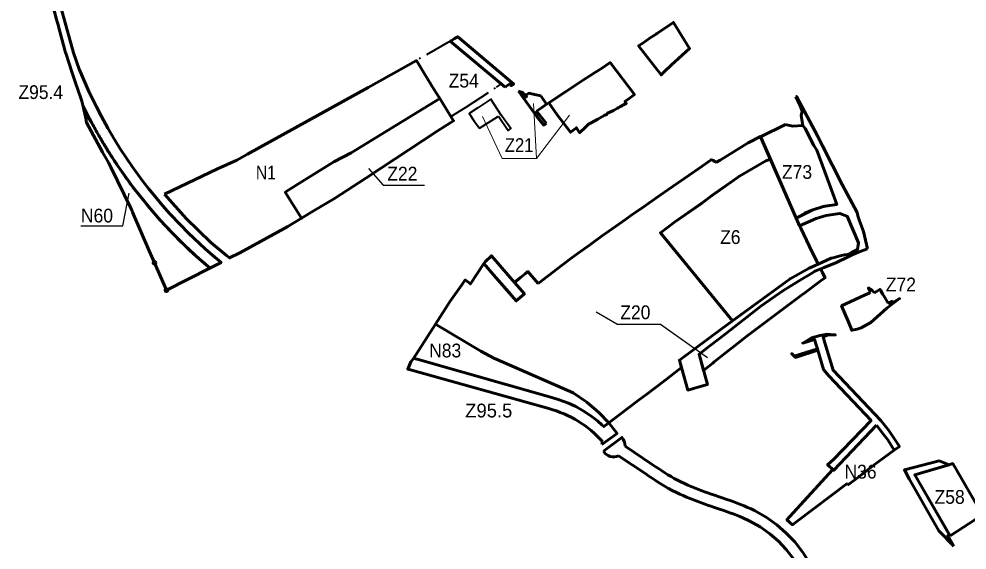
# Model space of a CAD drawing. Extents: x -650277 to -643422, y -1073980 to -1066720.
# Drawn here: x -649120 to -647467, y -1071620 to -1070696 of the extents above; entities that cross this region are included whole.
import ezdxf

# ---------------------------------------------------------------- set-up
doc = ezdxf.new("R2010")
doc.units = 0
doc.header["$LTSCALE"] = 9.6
doc.header["$PDMODE"] = 32
doc.header["$PDSIZE"] = 4.8
doc.linetypes.add('DOT_DASHED', pattern=[7.7, 5, -1.2, 0.3, -1.2])
for name, color, linetype, lineweight in [('1', 7, 'Continuous', 60), ('15', 7, 'Continuous', 60), ('18', 7, 'Continuous', 60), ('42', 7, 'Continuous', 60), ('60', 7, 'Continuous', 60), ('63', 7, 'Continuous', 25), ('7', 7, 'Continuous', 60), ('9', 7, 'Continuous', 60)]:
    doc.layers.add(name, color=color, linetype=linetype, lineweight=lineweight)

msp = doc.modelspace()

# ---------------------------------------------------------------- linework, layer by layer
at = {"layer": '1'}
for points in [[(-648032.601, -1070737.472), (-648039.82, -1070742.33), (-648000.85, -1070792.88), (-647994.63, -1070787.05), (-647982.89, -1070776.05), (-647976.97, -1070770.51), (-647964.21, -1070758.77), (-647951.11, -1070746.78), (-647979.17, -1070701.65), (-648008.28, -1070720.96), (-648009.29, -1070721.79), (-648019.49, -1070728.65)], [(-648540.7, -1070928.6), (-648571.14, -1070944.67), (-648634.07, -1070983.17), (-648655.76, -1070997.5), (-648627.39, -1071042.65), (-648605.3, -1071029.34), (-648570.23, -1071008.2), (-648515.46, -1070972.94), (-648389.33, -1070889.79), (-648362.519, -1070872.788), (-648386.587, -1070833.807), (-648479.18, -1070891.26)], [(-648215.08, -1071156.35), (-648232.8, -1071135.6), (-648237.46, -1071139.38), (-648245.49, -1071145.91), (-648256.04, -1071154.5), (-648238.84, -1071174.33), (-648253.126, -1071186.542), (-648292.587, -1071141.054), (-648309.41, -1071121.655), (-648333.002, -1071157.07), (-648341.943, -1071150.071), (-648347.949, -1071158.385), (-648368.48, -1071186.81), (-648394.104, -1071227.17), (-648315.127, -1071274.052), (-648292.406, -1071286.112), (-648274.918, -1071293.751), (-648154.21, -1071346.477), (-648130, -1071363), (-648109, -1071381), (-648091.92, -1071399.07), (-648060.01, -1071374.69), (-648038.18, -1071358.51), (-648025.39, -1071348.76), (-647994.31, -1071325.03), (-647965.26, -1071302.86), (-647966.226, -1071299.385), (-647968.896, -1071289.779), (-647916.208, -1071250.662), (-647895.959, -1071235.746), (-647875.939, -1071221.104), (-648001.922, -1071067.83), (-647977.41, -1071049.74), (-647930.96, -1071017.383), (-647912.11, -1071003.11), (-647864.29, -1070969.503), (-647818.33, -1070942.91), (-647810.243, -1070939.825), (-647827.527, -1070900.351), (-647848.89, -1070911.21), (-647897.76, -1070941.62), (-647904.13, -1070944.78), (-647909.42, -1070942.63), (-647908.63, -1070942.1), (-647913.45, -1070940.79), (-647934.9, -1070955.87), (-647952.01, -1070967.82), (-647970.19, -1070980.45), (-647988.81, -1070993.27), (-648008.34, -1071006.32), (-648030.24, -1071021.91), (-648044.82, -1071032.25), (-648051.48, -1071036.97), (-648062.53, -1071044.59), (-648085.73, -1071060.92), (-648097.61, -1071069.37), (-648102.55, -1071072.86), (-648125.53, -1071089.51), (-648141.12, -1071100.71), (-648155.77, -1071111.23), (-648172.48, -1071123.95), (-648197.57, -1071143.03)], [(-648001.922, -1071067.83), (-647977.41, -1071049.74), (-647930.7, -1071017.18), (-647911.838, -1071002.919), (-647864.03, -1070969.3), (-647864.03, -1070969.3), (-647818.33, -1070942.91), (-647810.243, -1070939.825), (-647759.52, -1071055.67), (-647757.19, -1071059.66), (-647742.64, -1071090.72), (-647726.74, -1071122.48), (-647742.35, -1071129.43), (-647775.982, -1071148.001), (-647775.982, -1071148.001), (-647875.939, -1071221.104)], [(-647756.03, -1071176.76), (-647750.34, -1071172.5), (-647726.56, -1071154.68), (-647723.79, -1071152.61), (-647720.85, -1071150.41), (-647714.71, -1071146.51), (-647719.73, -1071136.48), (-647722.51, -1071130.93), (-647732.58, -1071135.04), (-647733.38, -1071135.37), (-647737.027, -1071137.593), (-647761.366, -1071152.304), (-647788.66, -1071168.8), (-647826.56, -1071195.86), (-647889.22, -1071244.48), (-647915.6, -1071264.95), (-647934.6, -1071279.45), (-647926.69, -1071307.81), (-647910.73, -1071295.08), (-647907.92, -1071292.84), (-647888.77, -1071277.56), (-647873.25, -1071265.17), (-647850.956, -1071248.208)]]:
    msp.add_lwpolyline(points, close=True, dxfattribs=at)
at = {"layer": '1', "linetype": 'DOT_DASHED', "lineweight": 40}
msp.add_lwpolyline([(-648368.163, -1070734.376), (-648427.25, -1070767.95), (-648366.98, -1070865.44), (-648341.58, -1070849.98), (-648287.74, -1070814.32), (-648282.44, -1070810.84), (-648278.832, -1070808.761)], close=True, dxfattribs=at)
at = {"layer": '1'}
for points in [[(-648095.42, -1070860.3), (-648083.65, -1070854.89), (-648076.73, -1070851.07), (-648074.41, -1070849.79), (-648072.59, -1070848.79), (-648065.35, -1070844.8), (-648061.52, -1070842.68), (-648063.76, -1070839.49), (-648056.61, -1070834.26), (-648047.17, -1070827.35), (-648089.27, -1070771.57), (-648104.78, -1070781.65), (-648114.77, -1070788.08), (-648125.2, -1070794.79), (-648136.08, -1070801.79)], [(-648136.08, -1070801.79), (-648151.77, -1070812.11), (-648167.6, -1070822.53), (-648196.65, -1070841.7), (-648181.75, -1070862.74), (-648158.58, -1070892.98), (-648148.34, -1070884.92), (-648142.79, -1070893.78), (-648133.14, -1070884.6), (-648127, -1070878.75), (-648122.72, -1070876.44), (-648111.24, -1070870.11), (-648099.85, -1070863.82), (-648094.9, -1070861.09), (-648095.42, -1070860.3)], [(-648237.46, -1070829.68), (-648241.96, -1070823.46), (-648249.5, -1070821.08)], [(-648249.5, -1070821.08), (-648222.158, -1070859.221), (-648217.1, -1070865.56), (-648205.18, -1070880.5), (-648200.86, -1070877.05)], [(-648210.517, -1070829.445), (-648221.58, -1070827.03), (-648231.22, -1070824.92), (-648237.46, -1070829.68)], [(-648218.11, -1070856.44), (-648209.37, -1070850.44), (-648200.17, -1070844.094), (-648210.517, -1070829.445)], [(-648200.86, -1070877.05), (-648212.94, -1070862.74), (-648217.85, -1070856.93), (-648218.11, -1070856.44)]]:
    msp.add_lwpolyline(points, dxfattribs=at)
at = {"layer": '1', "lineweight": 40}
for points in [[(-648284.02, -1070864.91), (-648267.24, -1070889.9), (-648262.4, -1070886.58), (-648279.39, -1070862.98), (-648297.39, -1070835.36), (-648320.02, -1070850.16), (-648335.19, -1070860.49), (-648326.41, -1070873.55), (-648317.14, -1070885.48)], [(-648317.14, -1070885.48), (-648285.72, -1070865.96), (-648284.02, -1070864.91)]]:
    msp.add_lwpolyline(points, dxfattribs=at)
at = {"layer": '1'}
msp.add_point((-648237.46, -1070829.68), dxfattribs=at)
at = {"layer": '15'}
msp.add_line((-648272.453, -1070814.072), (-648271.1, -1070813.17), dxfattribs=at)
for points in [[(-648271.1, -1070813.17), (-648267.8, -1070810.96), (-648264.38, -1070808.66), (-648262.15, -1070811.96), (-648257.61, -1070808.91), (-648355.275, -1070726.455), (-648360.83, -1070729.87), (-648366.739, -1070733.501), (-648368.163, -1070734.376), (-648272.453, -1070814.072)], [(-647659.01, -1071032.66), (-647685.1, -1070983.93), (-647719.06, -1070916.45), (-647728.35, -1070899.11), (-647764.84, -1070830.47), (-647765.72, -1070830.64)], [(-647765.72, -1070830.64), (-647759.08, -1070845.74), (-647755.87, -1070853.02), (-647754.6, -1070856.11), (-647756.45, -1070863.95), (-647753.81, -1070881.3)], [(-647753.81, -1070881.3), (-647749.75, -1070886.1), (-647734.48, -1070915.94), (-647729.27, -1070924.35), (-647701.45, -1070999.4)], [(-647701.45, -1070999.4), (-647694.54, -1071018.549), (-647718, -1071022), (-647736, -1071028), (-647750, -1071034), (-647765.408, -1071042.223), (-647759.52, -1071055.67), (-647730.17, -1071043.21), (-647712.74, -1071037.99), (-647688.9, -1071034.18), (-647676.96, -1071039.014)], [(-647676.96, -1071039.014), (-647676.9, -1071039.03), (-647676.45, -1071039.22), (-647656.443, -1071085.369), (-647658.55, -1071097.02), (-647669.02, -1071102.33), (-647667.35, -1071106.38), (-647655.47, -1071100.98), (-647640.727, -1071095.819)], [(-647640.727, -1071095.819), (-647648.106, -1071065.551), (-647654.747, -1071047.095), (-647657.699, -1071038.232), (-647659.01, -1071032.66)], [(-647498.271, -1071593.544), (-647558.654, -1071489.738), (-647498.8, -1071471.94), (-647515.87, -1071465.25), (-647576.471, -1071481.091), (-647568.35, -1071496.656), (-647516.376, -1071586.89), (-647490.561, -1071613.609)], [(-647490.561, -1071613.609), (-647493.6, -1071608.5), (-647501.11, -1071595.45), (-647498.271, -1071593.544)]]:
    msp.add_lwpolyline(points, dxfattribs=at)
for points in [[(-647734.48, -1070915.94), (-647741.21, -1070902.78), (-647749.75, -1070886.1)], [(-647826.56, -1071195.86), (-647788.66, -1071168.8), (-647761.366, -1071152.304), (-647737.027, -1071137.593), (-647733.38, -1071135.37), (-647732.58, -1071135.04), (-647722.51, -1071130.93), (-647716.51, -1071128.48), (-647695.08, -1071119.72), (-647685.55, -1071115.14), (-647684.15, -1071114.47), (-647680.64, -1071112.77), (-647667.35, -1071106.38), (-647669.02, -1071102.33), (-647674.17, -1071104.97), (-647675.64, -1071105.71), (-647680.82, -1071106.54), (-647688.45, -1071108.38), (-647701.04, -1071111.41), (-647703.96, -1071112.11), (-647726.74, -1071122.48), (-647742.35, -1071129.43), (-647775.982, -1071148.001), (-647895.959, -1071235.746), (-647916.161, -1071250.628), (-647916.208, -1071250.662), (-647968.896, -1071289.779), (-647965.26, -1071302.86), (-647954.38, -1071342), (-647934.51, -1071336.37), (-647919.88, -1071332.23), (-647924.53, -1071315.55), (-647934.6, -1071279.45), (-647915.6, -1071264.95), (-647889.22, -1071244.48)], [(-648238.84, -1071174.33), (-648256.04, -1071154.5), (-648278.39, -1071128.74), (-648296.34, -1071108.04), (-648307.33, -1071118.47), (-648309.41, -1071121.655), (-648292.587, -1071141.054), (-648270.236, -1071166.815), (-648253.126, -1071186.542)], [(-647625.428, -1071403.267), (-647612.269, -1071419.742), (-647605.292, -1071428.816), (-647594.43, -1071446.543), (-647585.273, -1071440.044), (-647595.335, -1071424.564), (-647603.9, -1071412.1), (-647617.49, -1071394.901), (-647700.816, -1071307.512), (-647715.355, -1071259.885), (-647718.342, -1071248.972), (-647711.447, -1071246.332), (-647696.81, -1071245.79), (-647705.59, -1071245.08), (-647710.94, -1071244.65), (-647723.57, -1071246.66), (-647738.56, -1071251.13), (-647753.647, -1071260.178), (-647733.15, -1071254.081), (-647729.795, -1071265.066), (-647728.006, -1071269.975), (-647768.445, -1071282.6), (-647772.97, -1071278.43), (-647772.07, -1071279.33), (-647766.35, -1071285.11), (-647727.368, -1071272.362), (-647717.363, -1071306.29), (-647708.429, -1071316.821), (-647634.524, -1071394.901), (-647700.078, -1071462.96), (-647710.546, -1071472.023), (-647699.767, -1071481.617)]]:
    msp.add_lwpolyline(points, close=True, dxfattribs=at)
at = {"layer": '18'}
for points in [[(-647783.95, -1070879.58), (-647827.363, -1070900.725), (-647765.408, -1071042.223), (-647736, -1071028), (-647715.488, -1071021.631)], [(-647783.95, -1070879.58), (-647827.363, -1070900.725), (-647765.408, -1071042.223), (-647736, -1071028), (-647715.488, -1071021.631)], [(-647715.488, -1071021.631), (-647694.54, -1071018.549), (-647701.45, -1070999.4), (-647729.27, -1070924.35), (-647734.48, -1070915.94), (-647749.75, -1070886.1), (-647753.81, -1070881.3), (-647771.47, -1070882.27), (-647783.95, -1070879.58)], [(-647715.488, -1071021.631), (-647694.54, -1071018.549), (-647701.45, -1070999.4), (-647729.27, -1070924.35), (-647734.48, -1070915.94), (-647749.75, -1070886.1), (-647753.81, -1070881.3), (-647771.47, -1070882.27), (-647783.95, -1070879.58)]]:
    msp.add_lwpolyline(points, dxfattribs=at)
at = {"layer": '42'}
for p, q in [((-648883.73, -1071120.13), (-648862.97, -1071168.09)), ((-648862.97, -1071168.09), (-648787.207, -1071129.363))]:
    msp.add_line(p, q, dxfattribs=at)
for points in [[(-649002.97, -1070857.609), (-649007.885, -1070848.153), (-649003.1, -1070871.35), (-649002.82, -1070872.69), (-649002.62, -1070873.69), (-649002.15, -1070875.96), (-648974.4, -1070927.77), (-648963.5, -1070946.45), (-648959.92, -1070953.73), (-648948.29, -1070977.37), (-648924.92, -1071024.89), (-648922.98, -1071029.49), (-648921.87, -1071032.04), (-648892.82, -1071099.15), (-648883.73, -1071120.13)], [(-648994.42, -1070874.053), (-648994.464, -1070873.974), (-648994.52, -1070873.867)], [(-648982.403, -1070895.812), (-648982.467, -1070895.704), (-648982.524, -1070895.601)], [(-648970.64, -1070915.778), (-648970.712, -1070915.663), (-648970.771, -1070915.564)], [(-648960.194, -1070932.542), (-648960.268, -1070932.429), (-648960.34, -1070932.313)], [(-648949.345, -1070949.096), (-648949.389, -1070949.031), (-648949.428, -1070948.972)], [(-648939.179, -1070963.89), (-648939.232, -1070963.818), (-648939.33, -1070963.675)], [(-648918.464, -1070992.141), (-648918.601, -1070991.969), (-648918.737, -1070991.784)], [(-648292.406, -1071286.112), (-648315.127, -1071274.052), (-648394.104, -1071227.17), (-648432.093, -1071286.645)], [(-648432.093, -1071286.645), (-648426.18, -1071288.32), (-648191.25, -1071354.858)], [(-648091.92, -1071399.07), (-648109, -1071381), (-648130, -1071363), (-648154.21, -1071346.477), (-648274.918, -1071293.751), (-648292.406, -1071286.112)], [(-648191.25, -1071354.858), (-648178.158, -1071358.781), (-648162.084, -1071364.918), (-648149.571, -1071370.788), (-648136.263, -1071378.194), (-648123.313, -1071386.696), (-648111.646, -1071395.618), (-648103.268, -1071402.88), (-648100.438, -1071405.517), (-648091.92, -1071399.07)], [(-647625.428, -1071403.267), (-647699.767, -1071481.617), (-647701.415, -1071480.15), (-647708.18, -1071487.57), (-647776.13, -1071562.1)], [(-647676.51, -1071504.34), (-647674.28, -1071506.59), (-647656.27, -1071493.04), (-647626.7, -1071470.46), (-647611.82, -1071459.38), (-647594.43, -1071446.543), (-647605.292, -1071428.816), (-647612.269, -1071419.742), (-647625.428, -1071403.267)], [(-647776.13, -1071562.1), (-647781.31, -1071567.79), (-647771.717, -1071576.551), (-647764.23, -1071571.01), (-647676.51, -1071504.34)]]:
    msp.add_lwpolyline(points, dxfattribs=at)
for start, end in [(206.85611, 208.07207), (208.08607, 209.71957), (209.73567, 211.25686), (211.27351, 212.56631), (212.58435, 213.8879), (213.89777, 215.07157), (215.08899, 217.38409), (217.41391, 230.04071)]:
    msp.add_arc((-648232.695, -1070467.567), 863.398, start, end, dxfattribs=at)
for p in [(-648883.73, -1071120.13), (-648862.97, -1071168.09)]:
    msp.add_point(p, dxfattribs=at)
at = {"layer": '60'}
for points in [[(-649068.65, -1070642.23), (-649054.31, -1070696.44), (-649052.77, -1070702.25), (-649052.44, -1070703.48), (-649051.03, -1070708.74), (-649040.03, -1070750.06), (-649039.38, -1070752.51), (-649039.06, -1070753.72), (-649038.51, -1070755.38), (-649027.74, -1070787.51), (-649027.64, -1070787.8), (-649019.48, -1070812.18), (-649018.48, -1070815.18), (-649011.24, -1070836.79), (-649010.67, -1070838.5), (-649007.885, -1070848.153), (-648994.464, -1070873.974), (-648982.467, -1070895.704), (-648970.712, -1070915.663), (-648960.268, -1070932.429), (-648949.389, -1070949.031), (-648939.232, -1070963.818), (-648918.601, -1070991.969), (-648896.068, -1071020.184), (-648886.874, -1071031.044), (-648874.793, -1071044.773), (-648863.847, -1071056.723), (-648851.175, -1071069.886), (-648838.696, -1071082.562), (-648823.087, -1071097.562), (-648816.379, -1071103.782), (-648806.239, -1071112.938), (-648797, -1071121), (-648790.23, -1071126.818), (-648787.207, -1071129.363), (-648767.824, -1071119.455), (-648771.725, -1071116.233), (-648781.806, -1071107.721), (-648795.407, -1071095.8), (-648824.292, -1071068.677), (-648839.273, -1071053.556), (-648856.883, -1071034.761), (-648869.629, -1071020.411), (-648880.44, -1071007.703), (-648894.164, -1070990.806), (-648902.714, -1070979.812), (-648912.396, -1070966.893), (-648922.92, -1070952.242), (-648932.78, -1070937.887), (-648943.414, -1070921.659), (-648953.605, -1070905.299), (-648965.093, -1070885.794), (-648976.834, -1070864.527), (-648985.145, -1070848.538), (-648991.386, -1070835.954), (-648998.132, -1070821.723), (-649003.641, -1070809.566), (-649014.888, -1070782.994), (-649025.129, -1070754.377), (-649047.11, -1070674.743)], [(-648103.894, -1071436.836), (-648079.108, -1071418.564), (-648077.53, -1071417.4), (-648091.92, -1071399.07), (-648100.438, -1071405.517), (-648103.268, -1071402.88), (-648111.646, -1071395.618), (-648123.313, -1071386.696), (-648136.263, -1071378.194), (-648149.571, -1071370.788), (-648162.084, -1071364.918), (-648178.158, -1071358.781), (-648191.25, -1071354.858), (-648426.18, -1071288.32), (-648432.093, -1071286.645), (-648437.16, -1071292.53), (-648442.191, -1071305.453), (-648437.454, -1071306.778), (-648196.236, -1071374.226)], [(-648063.593, -1071439.723), (-648063.862, -1071435.078), (-648064.838, -1071431.28), (-648066.623, -1071427.592), (-648069.022, -1071424.443), (-648101.203, -1071448.31)], [(-648101.203, -1071448.31), (-648098.259, -1071452.196), (-648096.014, -1071454.192), (-648093.059, -1071456.066), (-648089.539, -1071457.489), (-648085.585, -1071458.248), (-648081.642, -1071458.215), (-648078.539, -1071457.636), (-648074.86, -1071456.248)], [(-647834.953, -1071553.406), (-647837.929, -1071551.872), (-647843.891, -1071549), (-647849.898, -1071546.282), (-647855.937, -1071543.707), (-647861.998, -1071541.254), (-647868.073, -1071538.911), (-647874.155, -1071536.658), (-647880.233, -1071534.48), (-647886.305, -1071532.36), (-647892.363, -1071530.282), (-647901.28, -1071527.249), (-647907.294, -1071525.204), (-647913.282, -1071523.152), (-647919.238, -1071521.081), (-647925.157, -1071518.976), (-647931.035, -1071516.824), (-647936.866, -1071514.613), (-647942.644, -1071512.329), (-647948.363, -1071509.96), (-647954.016, -1071507.496), (-647959.792, -1071504.833), (-647966.547, -1071501.883), (-647972.035, -1071499.009), (-647977.67, -1071495.885), (-647983.266, -1071492.628), (-647988.829, -1071489.259), (-647994.366, -1071485.79), (-647999.887, -1071482.241), (-648005.399, -1071478.627), (-648010.917, -1071474.963), (-648016.446, -1071471.268), (-648063.593, -1071439.723)], [(-648074.86, -1071456.248), (-648027.562, -1071487.894), (-648022.005, -1071491.607), (-648016.415, -1071495.321), (-648010.777, -1071499.017), (-648005.082, -1071502.678), (-647999.319, -1071506.287), (-647993.478, -1071509.826), (-647987.55, -1071513.275), (-647981.525, -1071516.615), (-647975.201, -1071519.929), (-647967.982, -1071523.081), (-647962.2, -1071525.746), (-647956.187, -1071528.368), (-647950.146, -1071530.869), (-647944.088, -1071533.263), (-647938.019, -1071535.566), (-647931.945, -1071537.788), (-647925.874, -1071539.949), (-647919.808, -1071542.058), (-647913.756, -1071544.132), (-647907.72, -1071546.185), (-647898.827, -1071549.208), (-647892.847, -1071551.26), (-647886.903, -1071553.336), (-647881.001, -1071555.45), (-647875.147, -1071557.619), (-647869.348, -1071559.856), (-647863.611, -1071562.177), (-647857.944, -1071564.594), (-647847.103, -1071569.497)], [(-647725.629, -1071678.373), (-647735.352, -1071657.117), (-647741.34, -1071644.028), (-647753.065, -1071625.201), (-647767.784, -1071606.225), (-647782.408, -1071590.847), (-647798.911, -1071576.526), (-647817.375, -1071563.458), (-647834.953, -1071553.406)], [(-647847.103, -1071569.497), (-647828.141, -1071580.34), (-647811.272, -1071592.28), (-647796.24, -1071605.324), (-647782.97, -1071619.278)], [(-647782.97, -1071619.278), (-647769.498, -1071636.647), (-647758.994, -1071653.513), (-647743.48, -1071687.426), (-647611.514, -1071974.086)]]:
    msp.add_lwpolyline(points, dxfattribs=at)
for centre, radius, start, end in [((-648244.965, -1071557.871), 190, 41.59858, 75.13936), ((-648083.781, -1071438.172), 20.157, 161.35794, 176.20098)]:
    msp.add_arc(centre, radius, start, end, dxfattribs=at)
at = {"layer": '63'}
msp.add_line((-648078, -1071227), (-648114, -1071206), dxfattribs=at)
at = {"layer": '63', "lineweight": 13}
for points in [[(-648223, -1070843), (-648217.945, -1070938.322), (-648277.841, -1070938.322), (-648311.985, -1070865.23)], [(-648277.841, -1070938.322), (-648217.945, -1070938.322), (-648160.135, -1070863.066)]]:
    msp.add_lwpolyline(points, dxfattribs=at)
at = {"layer": '63'}
for points in [[(-648511, -1070956), (-648485, -1070985), (-648413, -1070985)], [(-649012, -1071056), (-648939, -1071056), (-648928, -1070999)], [(-648078, -1071227), (-648002, -1071227), (-647920, -1071285)], [(-648078, -1071227), (-648002, -1071227), (-647920, -1071285)]]:
    msp.add_lwpolyline(points, dxfattribs=at)
at = {"layer": '7'}
msp.add_lwpolyline([(-648866.341, -1071000.881), (-648828.353, -1071043.265), (-648785.386, -1071084.634), (-648758.423, -1071107.756), (-648752.967, -1071111.861), (-648734.849, -1071102.599), (-648651.375, -1071057.109), (-648627.39, -1071042.65), (-648655.76, -1070997.5), (-648634.07, -1070983.17), (-648571.14, -1070944.67), (-648540.7, -1070928.6), (-648479.18, -1070891.26), (-648386.587, -1070833.807), (-648396.611, -1070817.573), (-648407.667, -1070799.667), (-648427.25, -1070767.95), (-648511.09, -1070814.7), (-648721.54, -1070930.88), (-648740.25, -1070941.21), (-648774.23, -1070956.42)], close=True, dxfattribs=at)
at = {"layer": '9'}
for points in [[(-647635.93, -1071171.22), (-647637.87, -1071173.29), (-647646.09, -1071176.68), (-647653.85, -1071179.87), (-647662.634, -1071183.968)], [(-647629.09, -1071172.4), (-647632.93, -1071167.71), (-647638.46, -1071163.89), (-647639.32, -1071164.22), (-647635.93, -1071171.22)], [(-647612.695, -1071177.542), (-647613.91, -1071175.57), (-647614.732, -1071174.222), (-647618.446, -1071168.166), (-647618.469, -1071168.129), (-647618.77, -1071167.64), (-647619.264, -1071166.832), (-647619.34, -1071166.709), (-647628.39, -1071172.05), (-647629.09, -1071172.4)], [(-647662.634, -1071183.968), (-647686.01, -1071195.35), (-647686.01, -1071195.35)], [(-647674.6, -1071221.71), (-647668.226, -1071237.571), (-647667.77, -1071237.5), (-647661.99, -1071236.62), (-647658.78, -1071235.63), (-647651.93, -1071233.57), (-647635.17, -1071224.18), (-647613.09, -1071204.33), (-647607.02, -1071199.34), (-647584.92, -1071182.54), (-647597.164, -1071189.857), (-647598.215, -1071187.608), (-647604.576, -1071190.781)], [(-647604.576, -1071190.781), (-647604.888, -1071190.272), (-647612.695, -1071177.542)], [(-647686.01, -1071195.35), (-647686.01, -1071195.35), (-647674.6, -1071221.71)]]:
    msp.add_lwpolyline(points, dxfattribs=at)
msp.add_lwpolyline([(-647497.04, -1071595.66), (-647440.67, -1071558.93), (-647492.3, -1071470), (-647495.85, -1071471.06), (-647558.654, -1071489.738)], close=True, dxfattribs=at)

# ---------------------------------------------------------------- texts
at = {"layer": '63'}
for s, width, p in [('Z54', 0.95, (-648371, -1070815)), ('Z95.4', 0.95, (-649121, -1070835)), ('Z21', 0.9, (-648272.998, -1070927.282)), ('N1', 0.85, (-648707, -1070975)), ('Z22', 0.95, (-648478, -1070977)), ('Z73', 0.95, (-647790, -1070974)), ('N60', 0.95, (-649012, -1071050)), ('Z6', 0.95, (-647897.847, -1071087.452)), ('Z6', 0.95, (-647897.847, -1071087.452)), ('Z72', 0.95, (-647609, -1071170)), ('Z20', 0.95, (-648071.847, -1071218.452)), ('Z20', 0.95, (-648071.847, -1071218.452)), ('N83', 0.95, (-648405, -1071285)), ('N36', 0.95, (-647681, -1071496)), ('Z58', 0.95, (-647524, -1071540))]:
    msp.add_text(s, height=24, dxfattribs=dict(at, width=width)).set_placement(p)
msp.add_text('Z95.5', height=24, dxfattribs=at).set_placement((-648342.123, -1071389.545))

doc.saveas('drawing.dxf')
